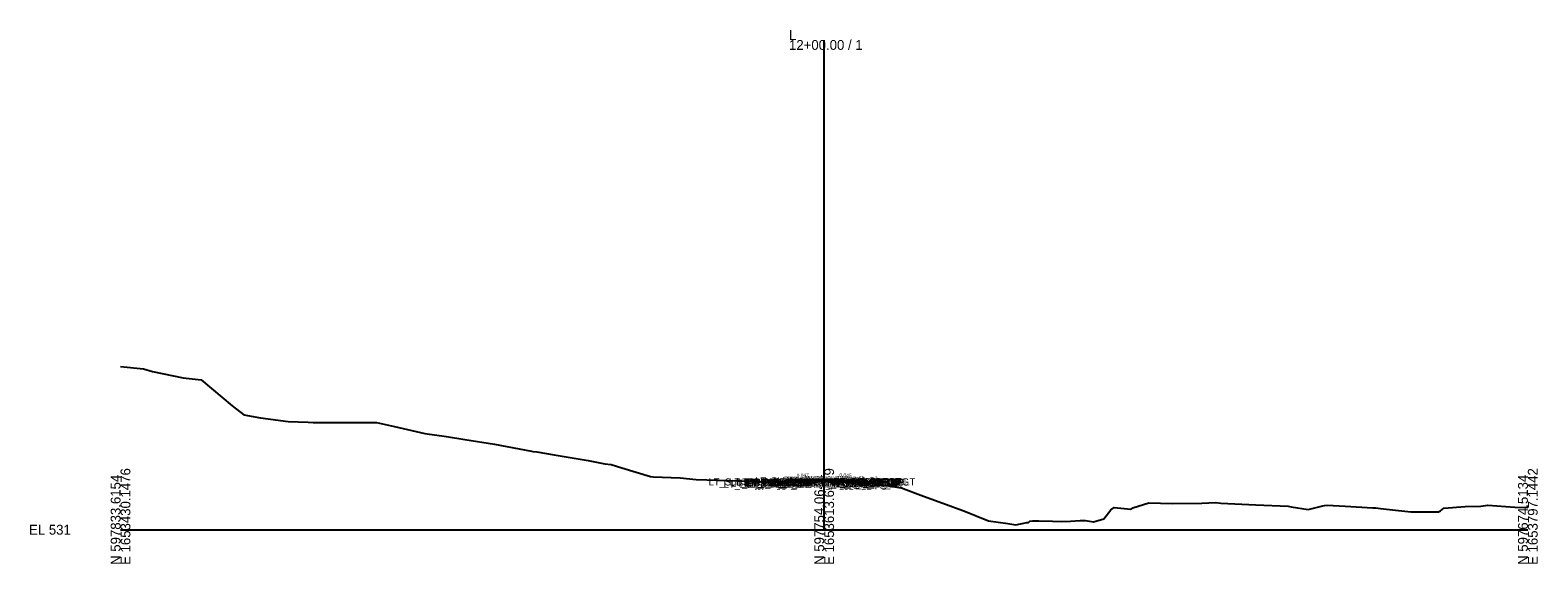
# Model space of a CAD drawing. Extents: x -26 to 403, y -10 to 6021.
# Drawn here: x -25.7 to 402.8, y 490.3 to 641.9 of the extents above; entities that cross this region are included whole.
import ezdxf

# ---------------------------------------------------------------- set-up
doc = ezdxf.new("R2010")
doc.units = 0
for name, color, linetype in [('Default', 7, 'Continuous'), ('Exist Cross Section Cell', 7, 'Continuous'), ('Exist XS Ground Line', 7, 'Continuous'), ('Prop CMT Pvmt Course 1', 7, 'Continuous'), ('Prop CMT Pvmt Course 2', 7, 'Continuous'), ('Prop CMT Pvmt Course 3', 7, 'Continuous'), ('Prop CMT Pvmt Surface', 7, 'Continuous'), ('Prop CMT Pvmt Surface Shoulder', 7, 'Continuous'), ('Prop CMT Pvmt Wedge Surface 1', 7, 'Continuous'), ('Prop CMT Pvmt Wedge Surface 2', 7, 'Continuous'), ('Prop CMT Pvmt Wedge Surface 3', 7, 'Continuous'), ('Prop CMT Shld Paved Course 1', 7, 'Continuous'), ('Prop CMT Shld Paved Course 2', 7, 'Continuous'), ('Prop CMT Shld Paved Course 3', 7, 'Continuous'), ('Prop CMT Slope Grass', 7, 'Continuous'), ('Prop CMT Subgrade Earthwork', 7, 'Continuous'), ('Prop XS Earthwork Shape', 7, 'Continuous'), ('Prop XS SE Text', 7, 'Continuous'), ('Prop XS Side Slope Text', 7, 'Continuous')]:
    doc.layers.add(name, color=color, linetype=linetype)

msp = doc.modelspace()

# ---------------------------------------------------------------- linework, layer by layer
at = {"layer": 'Exist Cross Section Cell'}
for p, q in [((200, 500), (200, 639.1)), ((0, 500), (200, 500)), ((200, 500), (400, 500))]:
    msp.add_line(p, q, dxfattribs=at)
at = {"layer": 'Exist XS Ground Line'}
msp.add_lwpolyline([(0, 546.37), (6.57, 545.66), (9.04, 544.96), (17.76, 543.17), (22.94, 542.6), (31.72, 535.15), (35.03, 532.67), (39.8, 531.8), (47.65, 530.75), (53.37, 530.53), (54.72, 530.5), (57.58, 530.41), (68.23, 530.47), (72.73, 530.43), (77.83, 529.36), (86.47, 527.34), (92.67, 526.47), (97.85, 525.58), (106.28, 524.28), (116.83, 522.29), (117.22, 522.25), (118.3, 522.16), (123.27, 521.27), (132.87, 519.67), (137.69, 518.75), (139.46, 518.48), (142.47, 517.61), (150.61, 515.1), (151.34, 515.06), (159.03, 514.69), (163.65, 514.27), (172.71, 513.98), (185.14, 513.51), (186.34, 513.48), (191.26, 513.71), (196.18, 513.98), (199.47, 514.13), (200, 514.11), (200.83, 514.07), (211.68, 513.6), (221.79, 511.93), (222.01, 511.89), (222.47, 511.7), (227.46, 509.78), (236.6, 506.51), (238.4, 505.87), (239.66, 505.33), (246.69, 502.54), (252.24, 501.79), (254.46, 501.35), (257.59, 502.04), (258.05, 502.05), (258.49, 502.41), (259.23, 502.5), (261, 502.54), (264.93, 502.47), (267.57, 502.36), (270.02, 502.41), (272.75, 502.62), (274.29, 502.62), (276.59, 502.27), (277.25, 502.4), (279.49, 503.07), (281.43, 505.64), (282.43, 506.28), (286.17, 505.92), (287.06, 505.88), (287.75, 506.17), (292.3, 507.65), (298.88, 507.43), (307.34, 507.55), (311.27, 507.7), (312.73, 507.56), (322.64, 507.1), (331.83, 506.66), (332.69, 506.54), (337.6, 505.72), (341.76, 506.81), (342.23, 506.89), (342.93, 506.95), (348.09, 506.66), (355.93, 506.21), (356.8, 506.23), (358.14, 506.04), (360.68, 505.74), (366.76, 505.03), (373.28, 505.03), (374.63, 505.03), (375.21, 505.36), (376.12, 506.16), (382.22, 506.57), (386.59, 506.68), (388.66, 507.01), (396.34, 506.43), (400, 506.27)], dxfattribs=at)
at = {"layer": 'Prop CMT Pvmt Course 1'}
for points in [[(200, 514.24), (188, 513.68)], [(200, 514.03), (200, 514.24)], [(200, 514.24), (212, 513.7)], [(200, 514.03), (200, 514.24)], [(188, 513.47), (200, 514.03)], [(188, 513.68), (188, 513.47), (188, 513.47), (188, 513.47)], [(200, 514.03), (200, 514.03), (200, 514.03)], [(211.68, 513.51), (200, 514.03)], [(200, 514.03), (200, 514.03), (200, 514.03)], [(212, 513.49), (211.68, 513.51)], [(211.68, 513.51), (211.68, 513.51)], [(212, 513.7), (212, 513.49)]]:
    msp.add_lwpolyline(points, dxfattribs=at)
at = {"layer": 'Prop CMT Pvmt Course 2'}
for points in [[(188, 513.26), (188, 513.26), (188, 513.47), (188, 513.47)], [(188, 513.47), (188, 513.26)], [(211.68, 513.3), (211.68, 513.51)], [(211.68, 513.51), (212, 513.49)], [(212, 513.28), (211.68, 513.3)], [(212, 513.49), (212, 513.28)]]:
    msp.add_lwpolyline(points, dxfattribs=at)
at = {"layer": 'Prop CMT Pvmt Course 3'}
for points in [[(188, 513.26), (188, 513.26), (188, 512.93), (188, 512.93)], [(188, 512.93), (188, 513.26)], [(211.68, 513.3), (212, 513.28)], [(211.68, 512.96), (211.68, 513.3)], [(212, 512.95), (211.68, 512.96)], [(212, 513.28), (212, 512.95)]]:
    msp.add_lwpolyline(points, dxfattribs=at)
at = {"layer": 'Prop CMT Pvmt Surface'}
for points in [[(200, 514.24), (188, 513.68)], [(200, 514.24), (212, 513.7)]]:
    msp.add_lwpolyline(points, dxfattribs=at)
at = {"layer": 'Prop CMT Pvmt Surface Shoulder'}
for points in [[(188, 513.68), (188, 513.68)], [(212, 513.7), (212, 513.7)]]:
    msp.add_lwpolyline(points, dxfattribs=at)
at = {"layer": 'Prop CMT Pvmt Wedge Surface 1'}
for points in [[(200, 514.24), (200, 514.03), (200, 514.03), (200, 514.03)], [(200, 514.24), (200, 514.03), (200, 514.03), (200, 514.03)], [(200, 514.03), (188, 513.47)], [(188, 513.47), (188, 513.68)], [(188, 513.47), (188, 513.47), (188, 513.47)], [(200, 514.03), (211.68, 513.51)], [(211.68, 513.51), (211.68, 513.51)], [(211.68, 513.51), (212, 513.49)], [(212, 513.49), (212, 513.7)]]:
    msp.add_lwpolyline(points, dxfattribs=at)
at = {"layer": 'Prop CMT Pvmt Wedge Surface 2'}
for points in [[(200, 514.24), (200, 514.03)], [(200, 514.24), (200, 514.03)], [(200, 514.03), (188, 513.47)], [(188, 513.47), (188, 513.68)], [(200, 514.03), (212, 513.49)], [(212, 513.49), (212, 513.7)]]:
    msp.add_lwpolyline(points, dxfattribs=at)
at = {"layer": 'Prop CMT Pvmt Wedge Surface 3'}
for points in [[(200, 514.24), (200, 513.82)], [(200, 514.24), (200, 513.82)], [(200, 513.82), (188, 513.26)], [(188, 513.26), (188, 513.68)], [(200, 513.82), (212, 513.28)], [(212, 513.28), (212, 513.7)]]:
    msp.add_lwpolyline(points, dxfattribs=at)
at = {"layer": 'Prop CMT Shld Paved Course 1'}
for points in [[(188, 513.68), (188, 513.68), (187.79, 513.46)], [(187.79, 513.46), (188, 513.47)], [(188, 513.47), (188, 513.68)], [(212, 513.7), (212, 513.7), (212.21, 513.49)], [(212, 513.49), (212, 513.7)], [(212.21, 513.49), (212, 513.49)]]:
    msp.add_lwpolyline(points, dxfattribs=at)
at = {"layer": 'Prop CMT Shld Paved Course 2'}
for points in [[(188, 513.47), (187.79, 513.46), (187.57, 513.25)], [(187.57, 513.25), (188, 513.26)], [(188, 513.26), (188, 513.47)], [(212, 513.49), (212.21, 513.49), (212.43, 513.27)], [(212, 513.28), (212, 513.49)], [(212.43, 513.27), (212, 513.28)]]:
    msp.add_lwpolyline(points, dxfattribs=at)
at = {"layer": 'Prop CMT Shld Paved Course 3'}
for points in [[(188, 513.26), (187.57, 513.25), (187.57, 513.25), (187.23, 512.91)], [(187.23, 512.91), (188, 512.93)], [(188, 512.93), (188, 513.26)], [(212, 513.28), (212.43, 513.27), (212.43, 513.27), (212.77, 512.93)], [(212, 512.95), (212, 513.28)], [(212.77, 512.93), (212, 512.95)]]:
    msp.add_lwpolyline(points, dxfattribs=at)
at = {"layer": 'Prop CMT Slope Grass'}
for points in [[(188, 513.68), (185.73, 513.49)], [(212, 513.7), (214, 513.54), (214.97, 513.05)]]:
    msp.add_lwpolyline(points, dxfattribs=at)
at = {"layer": 'Prop CMT Subgrade Earthwork'}
for points in [[(187.23, 512.91), (186.58, 513.56)], [(188, 512.93), (187.23, 512.91)], [(188, 512.93), (188.01, 513.56)], [(188, 512.93), (188, 512.93)], [(211.68, 512.96), (211.67, 513.6)], [(211.68, 512.96), (212, 512.95)], [(212, 512.95), (212.77, 512.93)], [(212.77, 512.93), (213.42, 513.59)]]:
    msp.add_lwpolyline(points, dxfattribs=at)
at = {"layer": 'Prop XS Earthwork Shape'}
for points in [[(185.73, 513.49), (186.34, 513.48), (186.65, 513.49), (186.58, 513.56)], [(185.73, 513.49), (186.34, 513.48), (186.65, 513.49), (186.58, 513.56)], [(185.73, 513.49), (186.34, 513.48), (186.65, 513.49), (186.58, 513.56)], [(188, 513.56), (188, 513.47), (188.01, 513.47), (188, 512.93), (187.23, 512.91), (186.65, 513.49)], [(188, 513.56), (188, 513.47), (188.01, 513.47), (188, 512.93), (187.23, 512.91), (186.65, 513.49)], [(188, 513.56), (188, 513.47), (188.01, 513.47), (188, 512.93), (187.23, 512.91), (186.65, 513.49)], [(188.01, 513.56), (191.26, 513.71), (196.18, 513.98), (199.47, 514.13), (200, 514.11), (200, 514.03), (188.01, 513.47)], [(188.01, 513.56), (191.26, 513.71), (196.18, 513.98), (199.47, 514.13), (200, 514.11), (200, 514.03), (188.01, 513.47)], [(188.01, 513.56), (191.26, 513.71), (196.18, 513.98), (199.47, 514.13), (200, 514.11), (200, 514.03), (188.01, 513.47)], [(211.67, 513.51), (200, 514.03), (200, 514.11), (200.83, 514.07), (211.67, 513.6)], [(211.67, 513.51), (200, 514.03), (200, 514.11), (200.83, 514.07), (211.67, 513.6)], [(211.67, 513.51), (200, 514.03), (200, 514.11), (200.83, 514.07), (211.67, 513.6)], [(211.67, 513.6), (211.68, 513.6), (212, 513.55), (212, 513.49), (211.68, 513.51), (211.67, 513.51)], [(211.67, 513.6), (211.68, 513.6), (212, 513.55), (212, 513.49), (211.68, 513.51), (211.67, 513.51)], [(211.67, 513.6), (211.68, 513.6), (212, 513.55), (212, 513.49), (211.68, 513.51), (211.67, 513.51)], [(212, 513.55), (213.18, 513.35), (212.77, 512.93), (212, 512.95), (211.68, 512.96), (211.67, 513.51), (211.68, 513.51), (212, 513.49)], [(212, 513.55), (213.18, 513.35), (212.77, 512.93), (212, 512.95), (211.68, 512.96), (211.67, 513.51), (211.68, 513.51), (212, 513.49)], [(212, 513.55), (213.18, 513.35), (212.77, 512.93), (212, 512.95), (211.68, 512.96), (211.67, 513.51), (211.68, 513.51), (212, 513.49)], [(213.18, 513.35), (214.97, 513.05), (214, 513.54), (213.42, 513.59)], [(213.18, 513.35), (214.97, 513.05), (214, 513.54), (213.42, 513.59)], [(213.18, 513.35), (214.97, 513.05), (214, 513.54), (213.42, 513.59)]]:
    msp.add_lwpolyline(points, close=True, dxfattribs=at)

# ---------------------------------------------------------------- texts
at = {"layer": 'Default'}
for s, height, p in [('LT_Sub_Trench_Out_DLT', 2, (167.15, 512.56)), ('LT_PV_Sub_Tie_Out', 2, (172.96, 512.56)), ('LT_PS3_Shelf_Out', 2, (173.56, 512.25)), ('LT_GS_OS_CTL', 2, (175.1, 512.49)), ('LT_PV_OEEOP_EG', 2, (175.54, 512.56)), ('LT_PV2_OEEOP', 2, (177.31, 512.47)), ('LT_PV3_OEEOP', 2, (177.31, 512.26)), ('LT_PS3_OEOP', 2, (177.81, 512.25)), ('LT_PV1_OEEOP', 2, (177.87, 512.47)), ('LT_PS2_OEOP', 2, (178.02, 512.46)), ('LT_PV2_OEOT', 2, (178.17, 512.47)), ('LT_PV3_OEOT', 2, (178.17, 512.26)), ('LT_PV1_OEOT', 2, (178.74, 512.68)), ('LT_PS1_OEOP', 2, (178.8, 512.68)), ('LT_PV_EG_TestPt', 2, (180.41, 512.86)), ('RT_PV_IEEOP_EG', 2, (188.14, 513.11)), ('LT_PV_IEEOP_EG', 2, (188.19, 513.11)), ('RT_PV2_IEEOP', 2, (189.91, 513.03)), ('RT_PV3_IEEOP', 2, (189.91, 512.82)), ('LT_PV2_IEEOP', 2, (189.95, 513.03)), ('LT_PV3_IEEOP', 2, (189.95, 512.82)), ('RT_PV1_IEEOP', 2, (190.47, 513.03)), ('LT_PV1_IEEOP', 2, (190.52, 513.03)), ('RT_PV_EG_TestPt', 2, (192.2, 512.85)), ('PV2_PGL', 2, (193.91, 513.03)), ('PV3_PGL', 2, (193.91, 512.82)), ('RT_Sub_Trench_Out_DLT', 2, (193.94, 512.59)), ('PV1_PGL', 2, (194.47, 513.24)), ('RT_PV_Sub_Tie_Out', 2, (196.57, 512.6)), ('RT_PS3_Shelf_Out', 2, (198.36, 512.27)), ('RT_PV_OEEOP_EG', 2, (199.18, 512.6)), ('RT_PV2_OEEOP', 2, (200.94, 512.51)), ('RT_PV3_OEEOP', 2, (200.94, 512.3)), ('RT_PV1_OEEOP', 2, (201.51, 512.51)), ('RT_PV2_OEOT', 2, (202.13, 512.49)), ('RT_PV3_OEOT', 2, (202.13, 512.28)), ('RT_PS2_OEOP', 2, (202.4, 512.49)), ('RT_PS3_OEOP', 2, (202.61, 512.27)), ('RT_PV1_OEOT', 2, (202.69, 512.7)), ('RT_PS1_OEOP', 2, (202.76, 512.7)), ('RT_GS_OS_CTL', 2, (203.32, 512.54)), ('LT_Sub_Trench_Out', 2, (171.44, 511.91)), ('LT_Sub_OEEOP', 2, (177.21, 511.93)), ('LT_Sub_OEOT', 2, (178.08, 511.93)), ('RT_Sub_Trench_Out', 2, (196.92, 511.93)), ('RT_Sub_OEEOP', 2, (200.85, 511.96)), ('RT_Sub_OEOT', 2, (202.03, 511.95)), ('RT_Slope_Fill', 2, (205.45, 512.05)), ('-', 0.0001, (0, 500))]:
    msp.add_text(s, height=height, dxfattribs=at).set_placement(p)
at = {"layer": 'Exist Cross Section Cell'}
for s, p in [('12+00.00 / 1', (190, 636.3)), ('L', (190, 639.1)), ('EL 531', (-26, 498.6))]:
    msp.add_text(s, height=2.8, dxfattribs=at).set_placement(p)
for s, p in [('N 597833.6154', (0, 490)), ('E 1653430.1476', (2.8, 490)), ('N 597754.0644', (200, 490)), ('E 1653613.6459', (202.8, 490)), ('N 597674.5134', (400, 490)), ('E 1653797.1442', (402.8, 490))]:
    msp.add_text(s, height=2.8, rotation=90, dxfattribs=at).set_placement(p)
at = {"layer": 'Prop XS SE Text'}
for s, rotation, p in [('0.047', 2.6909, (192.2, 514.87)), ('0.045', 357.4234, (204.31, 515.05))]:
    msp.add_text(s, height=1, rotation=rotation, dxfattribs=at).set_placement(p)
at = {"layer": 'Prop XS Side Slope Text'}
msp.add_text('2:1', height=1, rotation=333.4349, dxfattribs=at).set_placement((214.11, 514.32))

doc.saveas('drawing.dxf')
